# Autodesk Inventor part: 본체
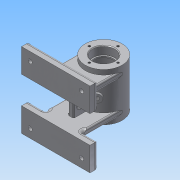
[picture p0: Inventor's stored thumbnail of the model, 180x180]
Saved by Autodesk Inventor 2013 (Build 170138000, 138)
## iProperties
Created: 2016-07
Part Number: 본체
Material: 알루미늄 6061
Document SubType Name: Modeling
Designer: Administrator
Density: 2.71 g/cm^3
Mass: 518.814 g
Surface Area: 552.241 cm^2
Volume: 191.444 cm^3
Author: Administrator
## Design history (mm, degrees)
sketch "스케치1"
  geometry: C1 r 27 at (0, 0); 1 further point
  constraints: 1 centre point, 1 coincident
  dimensions: "d0" = 54 diameter of C1
extrude "돌출1" new body sketch "스케치1" stored distance "d1" = 70; taper "d2" = 0 deg
hole "구멍1" diameter "d5" = 28; stored, may be unused: countersink angle "d9" = 90 deg, drill point angle "d11" = 0 deg; dims "d3" = 10, "d4" = 10, "d6" = 6, "d7" = 32, "d8" = 12, "d10" = 14
hole "구멍2" diameter "d14" = 28; stored, may be unused: countersink angle "d18" = 90 deg, drill point angle "d20" = 0 deg; dims "d12" = 10, "d13" = 10, "d15" = 6, "d16" = 44, "d17" = 42, "d19" = 44
hole "구멍3" diameter "d23" = 28; stored, may be unused: countersink angle "d27" = 90 deg, drill point angle "d29" = 0 deg; dims "d21" = 10, "d22" = 10, "d24" = 6, "d25" = 32, "d26" = 12, "d28" = 14
node "작업 평면1"
sketch "스케치2"
  geometry: L1 (50, 55)-(-50, 55); L2 (-50, 55)-(-50, 20); L3 (-50, 20)-(50, 20); L4 (50, 20)-(50, 55); L5 (50, -20)-(-50, -20); L6 (-50, -20)-(-50, -55); L7 (-50, -55)-(50, -55); L8 (50, -55)-(50, -20); 3 further points
  constraints: 16 end point, 4 parallel, 2 horizontal, 2 midpoint, 2 perpendicular, 2 vertical alignment
  dimensions: "d31" = 100 distance between parallel lines of L2 L4; "d33" = 100 distance between parallel lines of L6 L8; "d37" = 35 distance between parallel lines of L1 L3; "d38" = 35 distance between parallel lines of L5 L7; "d39" = 55 distance from line of L1 point (0, 0); "d40" = 55 distance from line of point (0, 0) L7
extrude "돌출2" join sketch "스케치2" distance "d41" = 12; taper "d42" = 0 deg
extrude "돌출3" join sketch "스케치2" distance "d43" = 12; taper "d44" = 0 deg
sketch "스케치3"
  geometry: L1 (50, -20)-(-50, -20) reference; L2 (-27, -28)-(27, -28); L3 (27, -28)-(27, -20); L4 (27, -20)-(-27, -20); L5 (-27, -20)-(-27, -28); 2 further points
  constraints: 8 end point, 2 midpoint, 2 parallel, 1 horizontal, 1 perpendicular
  dimensions: "d45" = 54 distance of L4.end L3.end; "d46" = 8 distance of L3.end L2.end
extrude "돌출4" join sketch "스케치3" stored distance "d47" = 12; taper "d48" = 0 deg
sketch "스케치4"
  geometry: L1 (-50, 20)-(50, 20) reference; L2 (27, 28)-(-27, 28); L3 (-27, 28)-(-27, 20); L4 (-27, 20)-(27, 20); L5 (27, 20)-(27, 28); 2 further points
  constraints: 8 end point, 2 midpoint, 2 parallel, 1 horizontal, 1 perpendicular
  dimensions: "d49" = 54 distance of L4.end L3.end; "d50" = 8 distance of L3.end L2.end
extrude "돌출5" join sketch "스케치4" stored distance "d51" = 12; taper "d52" = 0 deg
node "작업 평면3"
  node "작업 평면2"
sketch "스케치5"
  geometry: L1 (-4, 20)-(4, 20); L2 (4, 20)-(4, -20); L3 (4, -20)-(-4, -20); L4 (-4, -20)-(-4, 20); 4 further points
  constraints: 8 end point, 3 midpoint, 2 horizontal alignment, 2 parallel, 1 horizontal, 1 perpendicular, 1 vertical alignment
  dimensions: "d55" = 8 distance of L1.start L1.end; "d57" = 40 distance between parallel lines of L3 L1
extrude "돌출6" join sketch "스케치5" stored distance "d58" = 8; taper "d59" = 0 deg
sketch "스케치6"
  geometry: L1 (-3, 63.492)-(-15, 63.492) reference; L2 (-15, 63.492)-(-15, 74.702) reference; L3 (-15, 74.702)-(55, 74.702) reference; L4 (55, 74.702)-(55, 63.492) reference; L5 (55, 63.492)-(43, 63.492) reference; L6 (43, 63.492)-(43, 61.416) reference; L7 (43, 61.416)-(41, 61.416) reference; L8 (41, 61.416)-(41, 69.633) reference; L9 (41, 69.633)-(-1, 69.633) reference; L10 (-1, 69.633)-(-1, 61.416) reference; L11 (-1, 61.416)-(-3, 61.416) reference; L12 (-3, 61.416)-(-3, 63.492) reference; L13 (-35, -22)-(-35, -10) reference; L14 (-35, -10)-(-8, -10) reference; L15 (-8, -10)-(-8, 21.298) reference; L16 (-8, 21.298)-(-15, 21.298) reference; L17 (-15, 21.298)-(-15, 32.508) reference; L18 (-15, 32.508)-(-3, 32.508) reference; L19 (-3, 32.508)-(-3, 34.584) reference; L20 (-3, 34.584)-(-1, 34.584) reference; L21 (-1, 34.584)-(-1, 26.367) reference; L22 (-1, 26.367)-(41, 26.367) reference; L23 (41, 26.367)-(41, 34.584) reference; L24 (41, 34.584)-(43, 34.584) reference; L25 (43, 34.584)-(43, 32.508) reference; L26 (43, 32.508)-(55, 32.508) reference; L27 (55, 32.508)-(55, 21.298) reference; L28 (55, 21.298)-(48, 21.298) reference; L29 (48, 21.298)-(48, -10) reference; L30 (48, -10)-(75, -10) reference; L31 (75, -10)-(75, -22) reference; L32 (75, -22)-(40, -22) reference; L33 (40, -22)-(40, 0) reference; L34 (40, 0)-(0, 0) reference; L35 (0, 21.298)-(0, 0) reference; L36 (40, 21.298)-(0, 21.298) reference; L37 (40, 0)-(40, 21.298) reference; L38 (0, -22)-(-35, -22) reference; L39 (0, 0)-(0, -22) reference; L40 (12, 6.5)-(28, 6.5); L41 (28, 13.5)-(12, 13.5); L42 (20, 13.5)-(20, 6.5); L43 (-15, 75)-(-15, 21) reference; A1 r 3.5 centre (12, 10) between (12, 13.5) and (12, 6.5); A2 r 3.5 centre (28, 10) between (28, 6.5) and (28, 13.5); 1 further point
  constraints: 6 end point, 4 point on circle, 3 tangent, 2 centre point, 2 midpoint, 1 horizontal alignment
  dimensions: "d60" = 7 diameter of A1; "d61" = 7 diameter of A2; "d62" = 32 distance from line of L38 A1.centre; "d63" = 23 dimension on A2 A1; "d64" = 35 distance between parallel lines of L42 L43
extrude "돌출7" cut sketch "스케치6" stored distance "d65" = 8; taper "d66" = 0 deg
node "작업 평면5"
  node "작업 평면4"
sketch "스케치7"
  geometry: L1 (-27, -35)-(27, -35) reference; C1 r 5 at (0, -13); 1 further point
  constraints: 1 centre point, 1 vertical alignment
  dimensions: "d68" = 10 diameter of C1; "d70" = 22 distance from line of L1 C1.centre
extrude "돌출8" join sketch "스케치7" stored distance "d71" = 8; taper "d72" = 0 deg
sketch "스케치8"
  geometry: C1 r 5 at (0, 0) reference; 2 further points
  constraints: 1 coincident
hole "구멍4" sketch "스케치8" at (0, 0) diameter "d73" = 5.188; stored, may be unused: countersink angle "d77" = 90 deg, drill point angle "d79" = 0 deg; dims "d74" = 6, "d75" = 32, "d76" = 12, "d78" = 14
node "작업 평면6"
sketch "스케치9"
  geometry: L1 (0, 0)-(30, 0); L2 (0, 0)-(15.898, -25.441); L3 (0, 0)-(30, 0); L4 (4, -48)-(-4, -48) reference; L5 (-4, -48)-(-4, -41.5) reference; L6 (-4, -41.5)-(4, -41.5) reference; L7 (4, -41.5)-(4, -48) reference; L8 (4, -26.702)-(4, -34.5) reference; L9 (4, -34.5)-(-4, -34.5) reference; L10 (-4, -34.5)-(-4, -26.702) reference; C1 r 22 at (0, 0) reference; A1 r 27 centre (0, 0) between (4, -26.702) and (-4, -26.702) reference
  constraints: 6 end point, 2 horizontal, 1 equal length
  dimensions: "d83" = 30 distance of L1.start L2.end; "d84" = 58 deg angle of L2 L3
  node "절단 모서리 투영2"
node "작업 평면7"
sketch "스케치12"
  geometry: C1 r 16 at (0, 0) reference; 1 further point
  constraints: 1 vertical alignment
  dimensions: "d95" = 21 distance of C1.centre point (0, 21)
hole "구멍6" sketch "스케치12" at (0, 21) diameter "d96" = 3.242; stored, may be unused: countersink angle "d100" = 90 deg, drill point angle "d102" = 0 deg; dims "d97" = 8, "d98" = 32, "d99" = 12, "d101" = 10
sketch "스케치13"
  geometry: C1 r 16 at (0, 0) reference; 1 further point
  constraints: 1 vertical alignment
  dimensions: "d106" = 21 distance of C1.centre point (0, 21)
hole "구멍7" sketch "스케치13" at (0, 21) diameter "d107" = 3.242; stored, may be unused: countersink angle "d111" = 90 deg, drill point angle "d113" = 0 deg; dims "d108" = 8, "d109" = 32, "d110" = 12, "d112" = 10
sketch "스케치14"
  geometry: L1 (27, 20)-(50, 20) reference; L2 (50, 20)-(50, 55) reference; L3 (-50, 55)-(-50, 20) reference; L4 (-50, 20)-(-27, 20) reference; L5 (50, -55)-(50, -20) reference; L6 (-50, -20)-(-50, -55) reference; L7 (-27, -20)-(-50, -20) reference; L8 (50, -20)-(27, -20) reference; 5 further points
  dimensions: "d117" = 12.5 distance from line of L3 point (-37.5, 42.5); "d118" = 12.5 distance from line of L2 point (37.5, 42.5); "d119" = 12.5 distance from line of L5 point (37.5, -42.5); "d120" = 12.5 distance from line of L6 point (-37.5, -42.5); "d122" = 22.5 distance from line of L4 point (-37.5, 42.5); "d123" = 22.5 distance from line of L1 point (37.5, 42.5); "d124" = 22.5 distance from line of L7 point (-37.5, -42.5); "d125" = 22.5 distance from line of L8 point (37.5, -42.5)
hole "구멍8" sketch "스케치14" at (-37.5, 42.5), (37.5, 42.5), (-37.5, -42.5), (37.5, -42.5) diameter "d126" = 6; stored, may be unused: countersink angle "d130" = 90 deg, drill point angle "d132" = 0 deg; dims "d127" = 8, "d128" = 10, "d129" = 4, "d131" = 10
fillet "모깎기1" dims "d133" = 3
fillet "모깎기2" dims "d134" = 0.3
fillet "모깎기3" dims "d135" = 0.3
chamfer "모따기1" distance "d136" = 1; stored, may be unused: second distance "d137" = 2, angle "d138" = 110 deg
fillet "모깎기4" dims "d139" = 2
fillet "모깎기5" dims "d140" = 2
fillet "모깎기6" dims "d141" = 2
fillet "모깎기7" dims "d142" = 5
node "작업 평면8"
fillet "모깎기8" dims "d146" = 2
fillet "모깎기9" dims "d147" = 2
sketch "스케치16"
  geometry: L1 (-2, -41.5)-(2, -41.5) reference; L2 (4, -43.5)-(4, -46) reference; L3 (2, -48)-(-2, -48) reference; L4 (-4, -46)-(-4, -43.5) reference; L5 (4, -28.373)-(4, -32.5) reference; L6 (2, -34.5)-(-2, -34.5) reference; L7 (-4, -32.5)-(-4, -28.373) reference; L8 (0, 0)-(15.898, -25.441); L9 (0, 0)-(30, 0); C1 r 22 at (0, 0) reference; A1 r 2 centre (-2, -43.5) between (-2, -41.5) and (-4, -43.5) reference; A2 r 2 centre (2, -43.5) between (4, -43.5) and (2, -41.5) reference; A3 r 2 centre (2, -46) between (2, -48) and (4, -46) reference; A4 r 2 centre (-2, -46) between (-4, -46) and (-2, -48) reference; A5 r 27 centre (0, 0) between (5.586, -26.416) and (-5.586, -26.416) reference; A6 r 2 centre (6, -28.373) between (5.586, -26.416) and (4, -28.373) reference; A7 r 2 centre (2, -32.5) between (2, -34.5) and (4, -32.5) reference; A8 r 2 centre (-2, -32.5) between (-4, -32.5) and (-2, -34.5) reference; A9 r 2 centre (-6, -28.373) between (-4, -28.373) and (-5.586, -26.416) reference; 1 further point
  constraints: 4 end point, 1 equal length, 1 horizontal
  dimensions: "d148" = 30 distance of L8.start L8.end; "d149" = 58 deg angle of L8 L9
  node "절단 모서리 투영4"
node "작업 평면9"
sketch "스케치17"
  geometry: C1 r 6 at (0, 0); 1 further point
  constraints: 1 centre point, 1 coincident
  dimensions: "d150" = 12 diameter of C1
extrude "돌출10" join sketch "스케치17" stored distance "d151" = 8; taper "d152" = 0 deg
sketch "스케치18"
  geometry: C1 r 6 at (0, 0) reference; 1 further point
  constraints: 1 coincident
hole "구멍9" sketch "스케치18" at (0, 0) diameter "d153" = 5.188; stored, may be unused: countersink angle "d157" = 90 deg, drill point angle "d159" = 118 deg; dims "d154" = 8, "d155" = 10, "d156" = 4, "d158" = 10
node "작업 평면10"
sketch "스케치19"
  geometry: L1 (62.708, -20)-(70, -20) reference; L2 (70, -20)-(70, -55) reference; L3 (70, -55)-(63, -55) reference; L4 (58, -50)-(58, -29.464) reference; L5 (56, -26)-(0, -26) reference; L6 (0, -26)-(0, -22) reference; L7 (0, -22)-(0, 22) reference; L8 (53.764, 22)-(0, 22) reference; L9 (56, 25)-(56, 26) reference; L10 (58, 29.464)-(58, 50) reference; L11 (63, 55)-(70, 55) reference; L12 (70, 55)-(70, 20) reference; L13 (70, 20)-(62.708, 20) reference; L14 (53.764, -22)-(0, -22) reference; L15 (56, -26)-(56, -25) reference; L16 (0, -35)-(0, -26) reference; L17 (0, 22)-(0, 26) reference; L18 (56, 26)-(0, 26) reference; L19 (0, 26)-(0, 35) reference; A1 r 5 centre (63, -50) between (58, -50) and (63, -55) reference; A2 r 5 centre (63, 50) between (63, 55) and (58, 50) reference; 3 further points
  constraints: 1 coincident, 1 midpoint, 7 other
feature "엠보싱2" sketch "스케치19" dims "d11" = 0, "d31" = 100, "d37" = 35, "d39" = 55, "d40" = 55, "d120" = 12.5, "d124" = 22.5, "d147" = 2, "d160" = 0.5, "d161" = 0
node "솔리드1"
pattern_circular "원형 패턴1" dims angle "d104" = 360 deg
pattern_circular "원형 패턴2" dims angle "d115" = 360 deg
node "절단 모서리 투영1"
node "절단 모서리 투영5"
other parameters: "d53" = -21, "d67" = 3, "d80" = -35
